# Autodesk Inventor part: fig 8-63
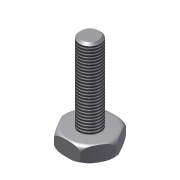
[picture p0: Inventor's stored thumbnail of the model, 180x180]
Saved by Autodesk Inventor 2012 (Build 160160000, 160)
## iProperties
Shininess: 77.0
Length Units: 11269
Angle Units: 11279
Time Units: 11290
Mass Units: 11283
Length Display Precision: 3
Angle Display Precision: 2
Created: 2002-01
Part Number: fig 8-63
Document SubType Name: Modeling
Designer: ***
Density: 1 g/cm^3
Material: Default
Density: 0.0
Volumn: 0.0
Area: 0.0
PropertySet Name: Model Information
Control State: 0
Master: False
Checked Out: False
Author: ***
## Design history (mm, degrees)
sketch "Sketch1"
  geometry: C1 r 25 at (0, 0)
  constraints: 1 centre point
  dimensions: "d0" = 50 diameter of C1
extrude "Extrusion1" new body sketch "Sketch1" distance "d1" = 15; taper "d2" = 0 deg
fillet "Fillet1" dims "d3" = 5
sketch "Sketch2"
  geometry: L1 (25.058, 0)-(12.529, -21.701); L2 (12.529, -21.701)-(-12.529, -21.701); L3 (-12.529, -21.701)-(-25.058, 0); L4 (-25.058, 0)-(-12.529, 21.701); L5 (-12.529, 21.701)-(12.529, 21.701); L6 (12.529, 21.701)-(25.058, 0); 1 further point
  constraints: 12 end point, 11 other
extrude "Extrusion2" sketch "Sketch2" stored distance "d4" = 15; taper "d5" = 0 deg
sketch "Sketch3"
  geometry: C1 r 10.044 at (0, 0); 1 further point
  constraints: 1 centre point, 1 coincident
extrude "Extrusion3" join sketch "Sketch3" distance "d6" = 75; taper "d7" = 0 deg
chamfer "Chamfer1" distance "d8" = 2; stored, may be unused: second distance "d9" = 2, angle "d16" = 45 deg
thread "Thread3" dims "d14" = 30, "d15" = 0
body "Solid1"
